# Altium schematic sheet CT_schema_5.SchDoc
size 145 x 123 mm
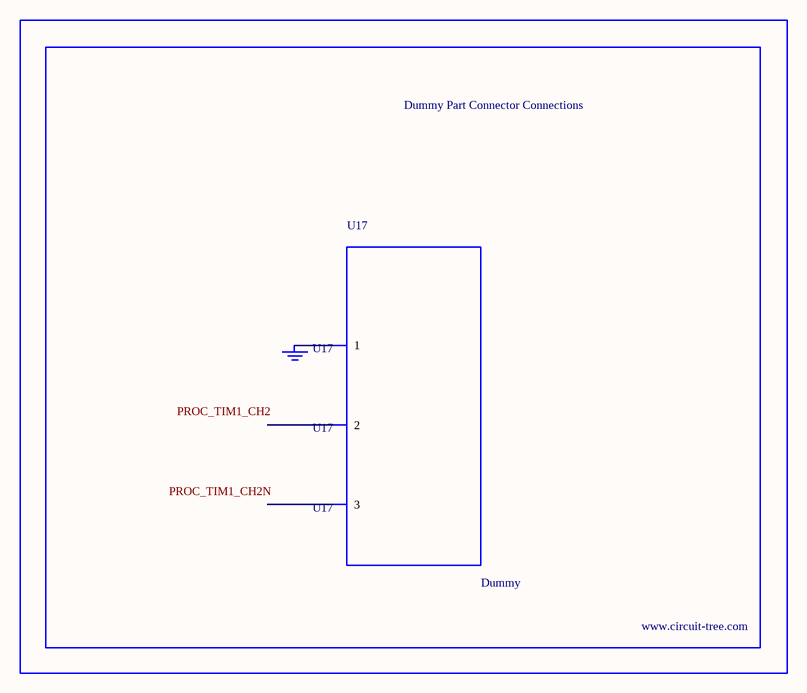
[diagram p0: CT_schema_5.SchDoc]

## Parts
BORDER4  (no value)
GND_INSTANCE_4_0  (no value)
U17  Dummy  [DUMMY_PACKAGE_160]

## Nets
NetGND_INSTANCE_4_0_0: GND_INSTANCE_4_0.0(GND) U17.1

Not connected (* = marked no-connect by the designer): U17 2 3

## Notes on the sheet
- Labels drawn without touching a wire or pin: PROC_TIM1_CH2, PROC_TIM1_CH2N

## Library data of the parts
BORDER4 = BORDER_PAGE4
GND_INSTANCE_4_0 = GND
